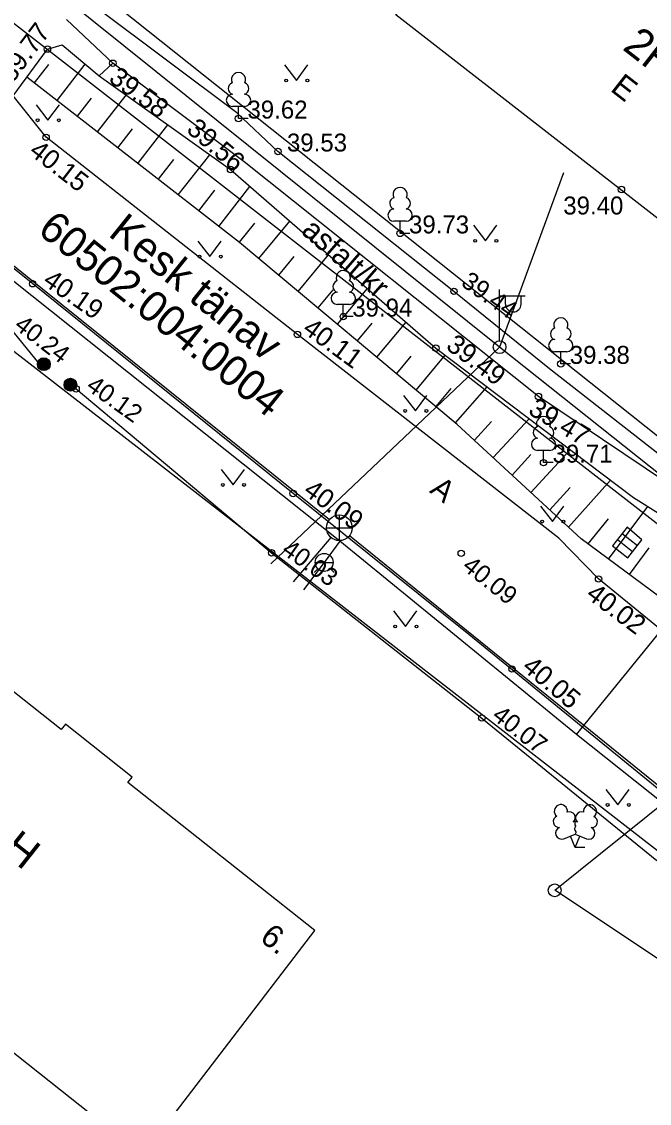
# Model space of a CAD drawing. Extents: x 641898 to 642452, y 6471715 to 6472255.
# Drawn here: x 642312.9 to 642337.37, y 6471802.88 to 6471845.1 of the extents above; entities that cross this region are included whole.
import ezdxf

# ---------------------------------------------------------------- set-up
doc = ezdxf.new("R2010")
doc.units = 0
for name, color, linetype in [('HALJASTUS', 7, 'Continuous'), ('HOONE', 7, 'Continuous'), ('KKAEV', 7, 'Continuous'), ('KORGUS-EH2000', 7, 'Continuous'), ('KTRASS', 7, 'Continuous'), ('MPOHULIIN', 7, 'Continuous'), ('PIIR', 7, 'Continuous'), ('POST', 7, 'Continuous'), ('PUU', 7, 'Continuous'), ('RELJEEF', 7, 'Continuous'), ('SIOHULIIN', 7, 'Continuous'), ('TEE', 7, 'Continuous'), ('VKAEV', 7, 'Continuous'), ('VTRASS', 7, 'Continuous')]:
    doc.layers.add(name, color=color, linetype=linetype)

msp = doc.modelspace()

# ---------------------------------------------------------------- linework, layer by layer
at = {"layer": 'HALJASTUS'}
for p, q in [((642323.148, 6471843.408), (642323.612, 6471842.801)), ((642323.612, 6471842.801), (642324.057, 6471843.408)), ((642313.458, 6471841.851), (642313.921, 6471841.244)), ((642313.921, 6471841.244), (642314.367, 6471841.851)), ((642330.519, 6471837.15), (642330.982, 6471836.543)), ((642330.982, 6471836.543), (642331.428, 6471837.15)), ((642319.771, 6471836.533), (642320.235, 6471835.926)), ((642320.235, 6471835.926), (642320.68, 6471836.533)), ((642327.788, 6471830.509), (642328.251, 6471829.903)), ((642328.251, 6471829.903), (642328.697, 6471830.509)), ((642320.678, 6471827.621), (642321.141, 6471827.014)), ((642321.141, 6471827.014), (642321.587, 6471827.621)), ((642333.132, 6471826.19), (642333.596, 6471825.584)), ((642333.596, 6471825.584), (642334.041, 6471826.19)), ((642327.402, 6471822.097), (642327.866, 6471821.49)), ((642327.866, 6471821.49), (642328.311, 6471822.097)), ((642335.683, 6471815.133), (642336.147, 6471814.527)), ((642336.147, 6471814.527), (642336.592, 6471815.133))]:
    msp.add_line(p, q, dxfattribs=at)
for points in [[(642288.49, 6471852.272), (642296.805, 6471845.864), (642304.75, 6471839.692), (642311.522, 6471834.256), (642313.79, 6471831.483)], [(642338.237, 6471827.832), (642333.487, 6471831.54), (642329.756, 6471834.57), (642322.893, 6471840.028), (642321.288, 6471841.543), (642315.856, 6471845.602)], [(642315.02, 6471830.765), (642322.645, 6471824.366), (642330.843, 6471817.92), (642337.665, 6471812.365)]]:
    msp.add_lwpolyline(points, dxfattribs=at)
for centre in [(642323.211, 6471842.801), (642324.039, 6471842.801), (642313.52, 6471841.244), (642314.349, 6471841.244), (642330.581, 6471836.543), (642331.41, 6471836.543), (642319.834, 6471835.926), (642320.663, 6471835.926), (642327.85, 6471829.903), (642328.679, 6471829.903), (642320.74, 6471827.014), (642321.569, 6471827.014), (642333.195, 6471825.584), (642334.023, 6471825.584), (642327.465, 6471821.49), (642328.294, 6471821.49), (642335.746, 6471814.527), (642336.574, 6471814.527)]:
    msp.add_circle(centre, 0.055, dxfattribs=at)
at = {"layer": 'HOONE'}
for points in [[(642341.045, 6471834.813), (642327.491, 6471845.358), (642330.674, 6471849.455), (642329.02, 6471850.529), (642329.906, 6471851.774), (642331.522, 6471850.559), (642332.775, 6471852.187), (642346.347, 6471841.629), (642341.045, 6471834.813)], [(642314.435, 6471817.467), (642307.082, 6471823.294), (642300.234, 6471814.661), (642317.624, 6471800.863), (642324.325, 6471809.63), (642317.037, 6471815.406), (642317.205, 6471815.618), (642314.604, 6471817.68), (642314.435, 6471817.467)]]:
    msp.add_lwpolyline(points, dxfattribs=at)
at = {"layer": 'KKAEV'}
for p, q in [((642325.287, 6471824.843), (642325.287, 6471825.843)), ((642324.787, 6471825.343), (642325.787, 6471825.343))]:
    msp.add_line(p, q, dxfattribs=at)
msp.add_circle((642325.287, 6471825.343), 0.5, dxfattribs=at)
at = {"layer": 'KORGUS-EH2000'}
for centre in [(642313.903, 6471844.023), (642316.454, 6471843.473), (642321.353, 6471841.314), (642313.851, 6471840.582), (642322.893, 6471840.028), (642321.043, 6471839.324), (642336.286, 6471838.545), (642327.653, 6471836.831), (642313.328, 6471834.865), (642329.756, 6471834.57), (642325.44, 6471833.585), (642323.652, 6471832.89), (642329.05, 6471832.354), (642333.92, 6471831.741), (642315.02, 6471830.765), (642333.05, 6471830.468), (642333.25, 6471827.886), (642323.486, 6471826.682), (642322.645, 6471824.366), (642330.039, 6471824.346), (642335.394, 6471823.345), (642332.018, 6471819.833), (642330.843, 6471817.92)]:
    msp.add_circle(centre, 0.125, dxfattribs=at)
at = {"layer": 'KTRASS'}
for points in [[(642324.897, 6471825.656), (642294.83, 6471849.849)], [(642365.181, 6471793.039), (642325.676, 6471825.028)], [(642323.492, 6471823.237), (642324.963, 6471824.962)]]:
    msp.add_lwpolyline(points, dxfattribs=at)
at = {"layer": 'MPOHULIIN'}
for points in [[(642355.522, 6471813.313), (642331.534, 6471832.393), (642302.222, 6471855.921), (642271.629, 6471880.301), (642234.793, 6471909.555), (642198.436, 6471939.015), (642169.975, 6471961.956), (642133.076, 6471995.171), (642102.99, 6472021.089), (642074.552, 6472045.947), (642044.597, 6472041.824), (642019.939, 6472060.923), (641980.015, 6472091.706), (641945.513, 6472065.466), (641932.178, 6472056.628)], [(642334.032, 6471839.195), (642331.534, 6471832.393)], [(642322.611, 6471823.936), (642331.534, 6471832.393)]]:
    msp.add_lwpolyline(points, dxfattribs=at)
at = {"layer": 'PIIR'}
for p, q in [((642294.31, 6471859.27), (642377.02, 6471794.87)), ((642357.49, 6471813.15), (642303.46, 6471856.17)), ((642344.1, 6471807.76), (642288.16, 6471851.19))]:
    msp.add_line(p, q, dxfattribs=at)
at = {"layer": 'POST'}
for p, q in [((642331.534, 6471832.643), (642331.534, 6471834.643)), ((642331.534, 6471834.393), (642332.534, 6471834.393)), ((642331.761, 6471834.072), (642331.761, 6471834.393)), ((642332.373, 6471834.072), (642332.373, 6471834.393))]:
    msp.add_line(p, q, dxfattribs=at)
for centre, radius in [((642331.534, 6471832.393), 0.25), ((642313.762, 6471831.727), 0.25), ((642313.762, 6471831.727), 0.225), ((642313.762, 6471831.727), 0.2), ((642313.762, 6471831.727), 0.175), ((642313.762, 6471831.727), 0.15), ((642313.762, 6471831.727), 0.125), ((642313.762, 6471831.727), 0.1), ((642313.762, 6471831.727), 0.075), ((642313.762, 6471831.727), 0.05), ((642313.762, 6471831.727), 0.025), ((642314.799, 6471830.926), 0.25), ((642314.799, 6471830.926), 0.225), ((642314.799, 6471830.926), 0.2), ((642314.799, 6471830.926), 0.175), ((642314.799, 6471830.926), 0.15), ((642314.799, 6471830.926), 0.125), ((642314.799, 6471830.926), 0.1), ((642314.799, 6471830.926), 0.075), ((642314.799, 6471830.926), 0.05), ((642314.799, 6471830.926), 0.025), ((642333.683, 6471811.198), 0.25)]:
    msp.add_circle(centre, radius, dxfattribs=at)
msp.add_arc((642332.067, 6471834.072), 0.306, 180, 0, dxfattribs=at)
at = {"layer": 'PUU'}
for p, q in [((642321.593, 6471841.789), (642321.113, 6471841.789)), ((642321.353, 6471841.314), (642321.353, 6471841.789)), ((642321.733, 6471841.314), (642321.353, 6471841.314)), ((642327.893, 6471837.306), (642327.413, 6471837.306)), ((642327.653, 6471836.831), (642327.653, 6471837.306)), ((642328.033, 6471836.831), (642327.653, 6471836.831)), ((642325.68, 6471834.06), (642325.2, 6471834.06)), ((642325.44, 6471833.585), (642325.44, 6471834.06)), ((642325.82, 6471833.585), (642325.44, 6471833.585)), ((642334.16, 6471832.216), (642333.68, 6471832.216)), ((642333.92, 6471831.741), (642333.92, 6471832.216)), ((642334.3, 6471831.741), (642333.92, 6471831.741)), ((642333.49, 6471828.361), (642333.01, 6471828.361)), ((642333.25, 6471827.886), (642333.25, 6471828.361)), ((642333.63, 6471827.886), (642333.25, 6471827.886)), ((642334.04, 6471813.208), (642334.485, 6471813.383)), ((642334.48, 6471812.873), (642334.305, 6471813.313)), ((642334.48, 6471812.873), (642334.66, 6471813.313)), ((642334.485, 6471813.383), (642334.925, 6471813.203)), ((642334.86, 6471812.873), (642334.48, 6471812.873))]:
    msp.add_line(p, q, dxfattribs=at)
msp.add_lwpolyline([(642334.485, 6471813.878), (642334.465, 6471813.803), (642334.465, 6471813.783), (642334.475, 6471813.753), (642334.495, 6471813.718), (642334.5, 6471813.698), (642334.485, 6471813.663), (642334.46, 6471813.613), (642334.455, 6471813.588), (642334.46, 6471813.573), (642334.47, 6471813.543), (642334.505, 6471813.483), (642334.51, 6471813.463), (642334.505, 6471813.443), (642334.49, 6471813.408), (642334.485, 6471813.383)], dxfattribs=at)
for centre, radius, start, end in [((642321.183, 6471842.487), 0.233, 109.0217, 253.1415), ((642321.353, 6471842.834), 0.277, 332.5799, 207.4201), ((642321.523, 6471842.487), 0.233, 286.8508, 70.9859), ((642321.116, 6471842.026), 0.238, 90.0016, 269.3953), ((642321.59, 6471842.026), 0.238, 270.6047, 89.9984), ((642327.653, 6471838.351), 0.277, 332.5799, 207.4201), ((642327.483, 6471838.004), 0.233, 109.0217, 253.1415), ((642327.823, 6471838.004), 0.233, 286.8508, 70.9859), ((642327.416, 6471837.543), 0.238, 90.0016, 269.3953), ((642327.89, 6471837.543), 0.238, 270.6047, 89.9984), ((642325.44, 6471835.105), 0.277, 332.5799, 207.4201), ((642325.27, 6471834.758), 0.233, 109.0217, 253.1415), ((642325.61, 6471834.758), 0.233, 286.8508, 70.9859), ((642325.203, 6471834.297), 0.238, 90.0016, 269.3953), ((642325.677, 6471834.297), 0.238, 270.6047, 89.9984), ((642333.92, 6471833.261), 0.277, 332.5799, 207.4201), ((642333.75, 6471832.914), 0.233, 109.0217, 253.1415), ((642334.09, 6471832.914), 0.233, 286.8508, 70.9859), ((642333.683, 6471832.453), 0.238, 90.0016, 269.3953), ((642334.157, 6471832.453), 0.238, 270.6047, 89.9984), ((642333.25, 6471829.406), 0.277, 332.5799, 207.4201), ((642333.08, 6471829.059), 0.233, 109.0217, 253.1415), ((642333.42, 6471829.059), 0.233, 286.8508, 70.9859), ((642333.013, 6471828.598), 0.238, 90.0016, 269.3953), ((642333.487, 6471828.598), 0.238, 270.6047, 89.9984), ((642333.923, 6471814.287), 0.256, 111.5027, 232.5173), ((642333.923, 6471814.287), 0.256, 350.4856, 111.5002), ((642335.059, 6471814.278), 0.256, 67.6168, 188.6314), ((642335.059, 6471814.278), 0.256, 306.5997, 67.6143), ((642333.849, 6471813.876), 0.224, 111.4304, 274.4987), ((642334.258, 6471814.037), 0.224, 308.5041, 111.5725), ((642334.721, 6471814.032), 0.225, 67.7016, 230.5126), ((642335.126, 6471813.866), 0.224, 264.6183, 67.6866), ((642333.954, 6471813.431), 0.237, 111.5014, 291.5004), ((642334.484, 6471813.64), 0.237, 66.7655, 111.5015), ((642335.015, 6471813.423), 0.237, 247.6166, 67.6155)]:
    msp.add_arc(centre, radius, start, end, dxfattribs=at)
at = {"layer": 'RELJEEF'}
for p, q in [((642313.397, 6471842.701), (642313.957, 6471843.42)), ((642314.276, 6471842.017), (642315.379, 6471843.433)), ((642315.609, 6471842.106), (642315.062, 6471841.404)), ((642315.851, 6471840.79), (642316.971, 6471842.227)), ((642317.429, 6471839.561), (642318.601, 6471841.065)), ((642317.213, 6471840.91), (642316.64, 6471840.175)), ((642319.007, 6471838.332), (642320.231, 6471839.903)), ((642318.817, 6471839.715), (642318.218, 6471838.946)), ((642320.421, 6471838.519), (642319.796, 6471837.717)), ((642320.585, 6471837.103), (642321.801, 6471838.664)), ((642321.977, 6471837.237), (642321.373, 6471836.488)), ((642322.141, 6471835.848), (642323.36, 6471837.307)), ((642323.676, 6471834.565), (642324.869, 6471835.993)), ((642323.512, 6471835.928), (642322.909, 6471835.206)), ((642325.211, 6471833.283), (642326.378, 6471834.68)), ((642325.034, 6471834.63), (642324.444, 6471833.924)), ((642326.555, 6471833.332), (642325.978, 6471832.642)), ((642326.746, 6471832.001), (642327.887, 6471833.366)), ((642328.077, 6471832.035), (642327.513, 6471831.359)), ((642328.281, 6471830.718), (642329.416, 6471832.077)), ((642329.631, 6471830.775), (642329.048, 6471830.077)), ((642329.815, 6471829.436), (642331.047, 6471830.843)), ((642331.219, 6471829.485), (642330.553, 6471828.761)), ((642331.287, 6471828.082), (642332.69, 6471829.6)), ((642332.756, 6471826.724), (642334.293, 6471828.387)), ((642332.756, 6471828.198), (642332.021, 6471827.403)), ((642334.224, 6471825.367), (642335.86, 6471827.201)), ((642334.292, 6471826.913), (642333.49, 6471826.045)), ((642335.785, 6471824.12), (642337.31, 6471826.177)), ((642335.766, 6471825.697), (642334.982, 6471824.715)), ((642337.357, 6471824.561), (642336.589, 6471823.525))]:
    msp.add_line(p, q, dxfattribs=at)
msp.add_lwpolyline([(642358.168, 6471807.514), (642356.92, 6471807.766), (642351.592, 6471812.066), (642342.878, 6471818.864), (642334.715, 6471824.913), (642329.886, 6471829.377), (642321.394, 6471836.472), (642313.104, 6471842.93)], dxfattribs=at)
at = {"layer": 'SIOHULIIN'}
msp.add_lwpolyline([(642382.916, 6471799.858), (642363.199, 6471791.543), (642333.683, 6471811.198), (642353.478, 6471827.095)], dxfattribs=at)
at = {"layer": 'TEE'}
for p, q in [((642336.906, 6471824.634), (642336.317, 6471825.105)), ((642336.718, 6471824.399), (642336.129, 6471824.87))]:
    msp.add_line(p, q, dxfattribs=at)
for points in [[(642366.559, 6471781.691), (642366.75, 6471785.551), (642365.695, 6471788.509), (642364.88, 6471791.554), (642359.32, 6471797.565), (642349.55, 6471805.814), (642345.029, 6471809.364), (642338.375, 6471814.612), (642330.338, 6471821.174), (642323.486, 6471826.682), (642313.328, 6471834.865), (642303.076, 6471843.066), (642293.352, 6471850.788), (642283.707, 6471858.589), (642276.578, 6471864.269), (642271.231, 6471868.612), (642264.701, 6471873.908), (642253.944, 6471882.162), (642243.566, 6471890.342)], [(642383.211, 6471751.926), (642385.791, 6471761.757), (642386.251, 6471768.397), (642385.085, 6471777.246), (642381.999, 6471784.94), (642376.754, 6471790.765), (642370.195, 6471795.981), (642371.442, 6471797.485), (642368.827, 6471798.665), (642362.827, 6471801.747), (642353.417, 6471808.678), (642343.817, 6471816.473), (642335.394, 6471823.345), (642333.841, 6471824.933), (642323.652, 6471832.89), (642313.851, 6471840.582), (642312.566, 6471842.194), (642313.903, 6471844.023), (642314.481, 6471844.192), (642315.921, 6471842.975), (642316.454, 6471843.473), (642314.647, 6471845.18)], [(642315.921, 6471842.975), (642321.043, 6471839.324), (642329.05, 6471832.354), (642336.751, 6471826.527), (642337.832, 6471825.85), (642353.612, 6471812.259), (642353.604, 6471812.269), (642354.098, 6471812.513), (642356.853, 6471809.472), (642358.168, 6471807.514), (642358.699, 6471807.804), (642358.121, 6471809.863), (642356.774, 6471811.304), (642352.656, 6471814.372), (642345.639, 6471820.471), (642338.503, 6471826.585), (642339.912, 6471828.256), (642339.384, 6471828.665), (642338.042, 6471827.11), (642333.05, 6471830.468), (642321.569, 6471839.628), (642316.454, 6471843.473)], [(642336.531, 6471824.165), (642337.078, 6471824.877), (642336.503, 6471825.363), (642335.942, 6471824.636), (642336.531, 6471824.165)]]:
    msp.add_lwpolyline(points, dxfattribs=at)
at = {"layer": 'VKAEV'}
for p, q in [((642324.447, 6471823.745), (642324.307, 6471823.605)), ((642324.344, 6471823.992), (642325.044, 6471823.992)), ((642324.941, 6471823.745), (642325.081, 6471823.605))]:
    msp.add_line(p, q, dxfattribs=at)
msp.add_circle((642324.694, 6471823.992), 0.35, dxfattribs=at)
at = {"layer": 'VTRASS'}
for points in [[(642383.722, 6471805.593), (642379.745, 6471805.698), (642375.961, 6471804.651), (642372.001, 6471801.12), (642371.83, 6471800.837), (642365.292, 6471792.802), (642334.532, 6471817.276), (642325.31, 6471824.815), (642293.796, 6471849.944), (642275.212, 6471864.371), (642256.629, 6471878.798), (642256.057, 6471879.253), (642241.436, 6471890.95)], [(642334.532, 6471817.276), (642340.942, 6471825.162), (642344.21, 6471829.41), (642341.513, 6471831.471), (642342.436, 6471832.732)], [(642325.31, 6471824.815), (642324.694, 6471823.992), (642323.891, 6471822.92)]]:
    msp.add_lwpolyline(points, dxfattribs=at)

# ---------------------------------------------------------------- texts
at = {"layer": 'HOONE'}
for s, height, rotation, p in [('2H', 1.2, 322.1191, (642336.289, 6471844.032)), ('E', 0.9, 322.1191, (642335.814, 6471842.418)), ('H', 1.2, 321.5719, (642312.082, 6471812.673)), ('6.', 0.9, 321.5719, (642322.142, 6471809.262))]:
    msp.add_text(s, height=height, rotation=rotation, dxfattribs=at).set_placement(p)
at = {"layer": 'KORGUS-EH2000'}
for s, height, rotation, p in [('39.77', 0.75, 53.2127, (642312.546, 6471842.67)), ('39.58', 0.75, 323.4267, (642316.25, 6471842.785)), ('39.56', 0.75, 319.4896, (642319.284, 6471840.821)), ('40.15', 0.75, 322.2583, (642313.144, 6471839.944)), ('40.19', 0.75, 325.228, (642313.678, 6471834.865)), ('39.44', 0.7, 324.5254, (642329.989, 6471834.822)), ('40.24', 0.7, 322.3829, (642312.566, 6471833.153)), ('40.11', 0.75, 323.979, (642323.806, 6471832.994)), ('39.49', 0.75, 323.1907, (642329.4, 6471832.354)), ('40.12', 0.7, 324.5438, (642315.37, 6471830.765)), ('39.47', 0.75, 329.0931, (642332.606, 6471829.811)), ('40.09', 0.75, 324.0574, (642323.836, 6471826.682)), ('40.03', 0.7, 324.78, (642322.995, 6471824.366)), ('40.09', 0.7, 321.418, (642330.037, 6471823.758)), ('40.02', 0.75, 323.1136, (642334.862, 6471822.645)), ('40.05', 0.75, 320.1775, (642332.368, 6471819.833)), ('40.07', 0.7, 322.1083, (642331.193, 6471817.92))]:
    msp.add_text(s, height=height, rotation=rotation, dxfattribs=at).set_placement(p)
for s, p in [('39.62', (642321.703, 6471841.314)), ('39.53', (642323.243, 6471840.028)), ('39.40', (642334.018, 6471837.57)), ('39.73', (642328.003, 6471836.831)), ('39.94', (642325.79, 6471833.585)), ('39.38', (642334.27, 6471831.741)), ('39.71', (642333.6, 6471827.886))]:
    msp.add_text(s, height=0.7, dxfattribs=at).set_placement(p)
at = {"layer": 'PIIR'}
for s, p in [('60502:004:0004', (642313.471, 6471836.869)), ('Kesk tänav', (642316.234, 6471836.762))]:
    msp.add_text(s, height=1.2, rotation=321.2362, dxfattribs=at).set_placement(p)
at = {"layer": 'TEE'}
for s, rotation, p in [('asfalt/kr', 318.9608, (642323.761, 6471836.859)), ('A', 322.0123, (642328.771, 6471826.746))]:
    msp.add_text(s, height=0.85, rotation=rotation, dxfattribs=at).set_placement(p)

doc.saveas('drawing.dxf')
